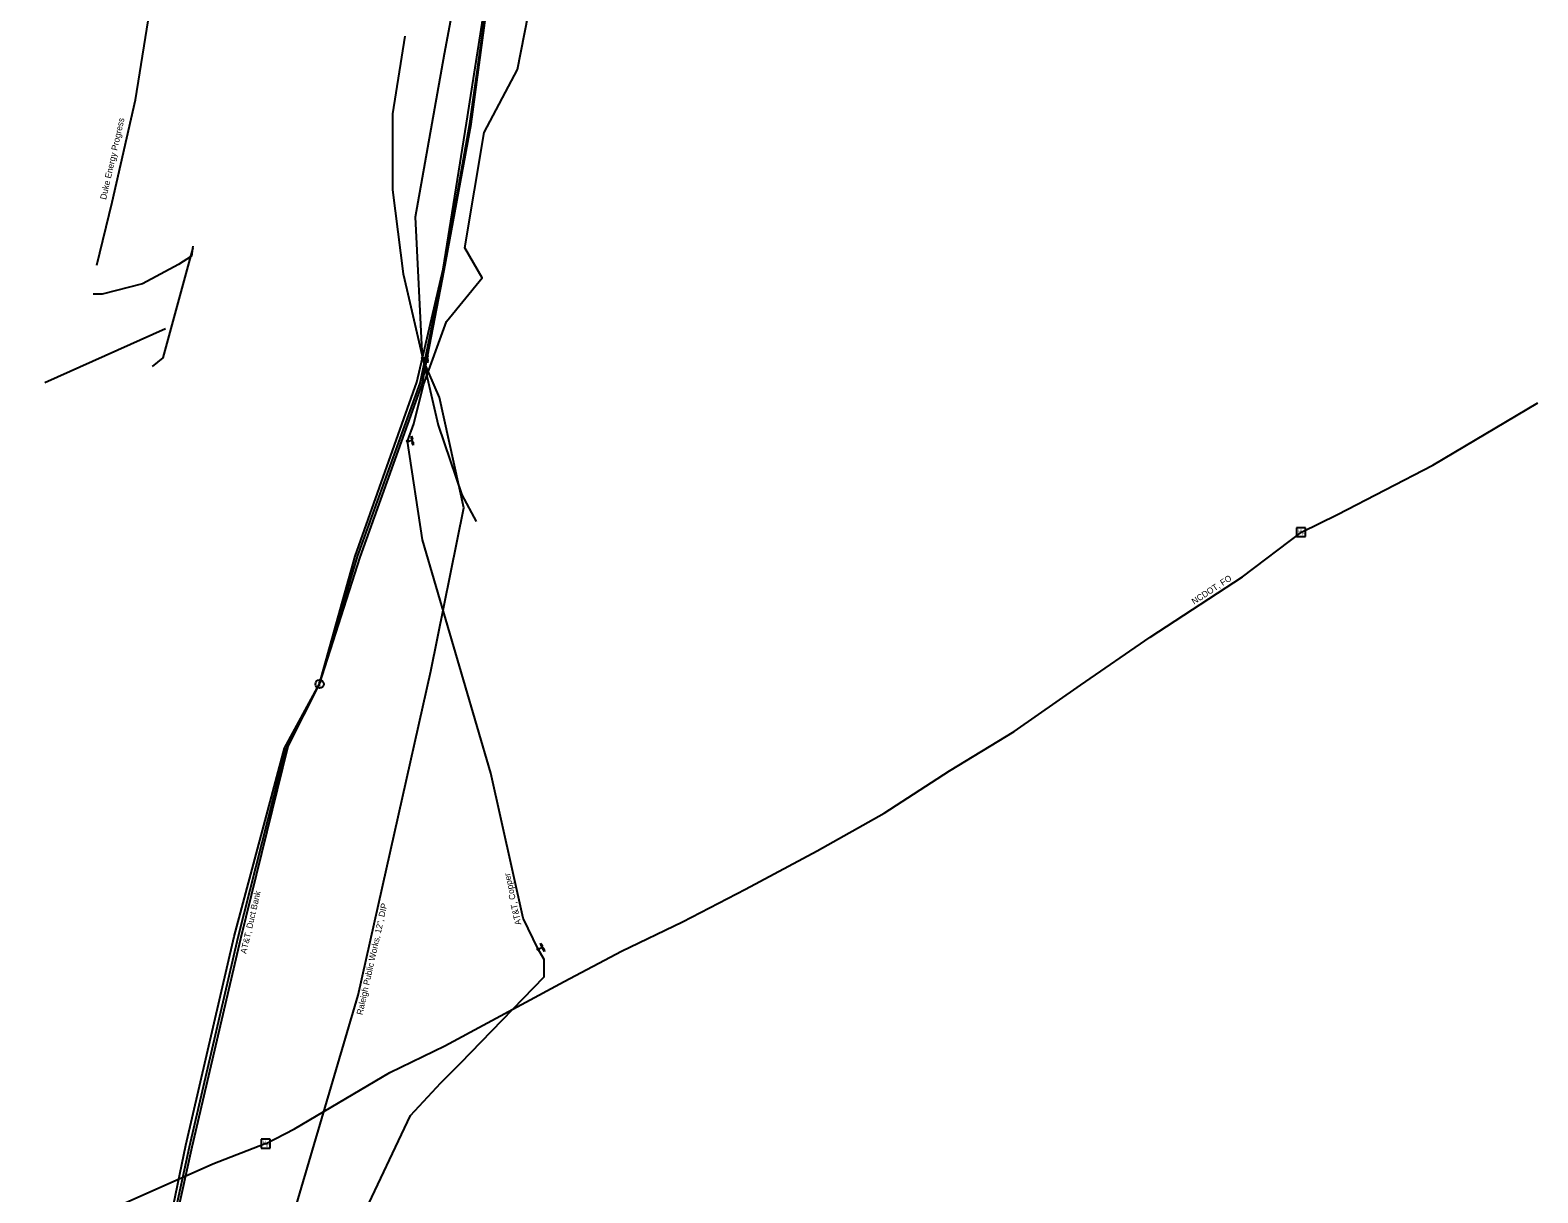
# Model space of a CAD drawing. Extents: x 2070721 to 2083039, y 729290 to 737883.
# Drawn here: x 2082068 to 2083039, y 735399 to 736148 of the extents above; entities that cross this region are included whole.
import ezdxf

# ---------------------------------------------------------------- set-up
doc = ezdxf.new("R2010")
doc.units = 0
for name, color, linetype in [('Exist Utilities Gas UG Line SUE LOS B Cogo Comment', 7, 'Continuous'), ('Exist Utilities Gas Valve CELL', 7, 'Continuous'), ('Exist Utilities Power Pole CELL', 7, 'Continuous'), ('Exist Utilities Power Pole Cogo Elevation', 7, 'Continuous'), ('Exist Utilities Power UG Cable SUE LOS B Cogo Number', 7, 'Continuous'), ('Exist Utilities Telephone UG Cable SUE LOS C Cogo Point CELL', 7, 'Continuous'), ('Exist Utilities Telephone UG FO SUE LOS B Cogo Number', 7, 'Continuous'), ('Exist Utilities TV Hand Hole Cogo Elevation', 7, 'Continuous'), ('Exist Utilities TV Hand Hole Cogo Number', 7, 'Continuous'), ('Exist Utilities TV Pedestal Cogo Elevation', 7, 'Continuous'), ('Exist Utilities TV UG Cable SUE LOS C Cogo Comment', 7, 'Continuous'), ('Exist Utilities TV UG Cable SUE LOS C Cogo Point CELL', 7, 'Continuous'), ('Exist Utilities Water Fire Hydrant Cogo Elevation', 7, 'Continuous'), ('Exist Utilities Water Meter CELL', 7, 'Continuous'), ('Exist Utilities Water UG Line SUE Cogo Point CELL', 7, 'Continuous'), ('Exist Utilities Water UG Line SUE LOS B Cogo Point CELL', 7, 'Continuous')]:
    doc.layers.add(name, color=color, linetype=linetype)

msp = doc.modelspace()

# ---------------------------------------------------------------- linework, layer by layer
at = {"layer": 'Exist Utilities Gas Valve CELL'}
msp.add_line((2082154.94, 735955.71), (2082077.21, 735921.08), dxfattribs=at)
at = {"layer": 'Exist Utilities Power Pole CELL'}
for points in [[(2082121.11, 735111.12), (2082125.96, 735163.62), (2082138.7, 735257.13), (2082145.62, 735320.66), (2082168.01, 735429.9), (2082199.18, 735564.38), (2082231.58, 735685.7), (2082254.18, 735727.05), (2082277.17, 735809.42), (2082316.95, 735921.54), (2082334, 735994.14), (2082349.07, 736088.38), (2082364.7, 736188.68), (2082369.94, 736249.54)], [(2082122.2, 735109.35), (2082127.71, 735163.64), (2082140.55, 735257.07), (2082148.23, 735320.74), (2082172.1, 735428.75), (2082203.63, 735562.9), (2082234.11, 735686.98), (2082254.24, 735726.85), (2082280.4, 735808.61), (2082320.45, 735920.23), (2082334.66, 735993.58), (2082351.98, 736087.59), (2082365.57, 736188.21), (2082370.28, 736249.44)], [(2082311, 735883.41), (2082314.93, 735894.57), (2082321.33, 735919.82), (2082336.09, 735960.51), (2082359.13, 735988.75), (2082348, 736007.91), (2082360.44, 736082.28), (2082381.79, 736122.83), (2082393.52, 736182.23), (2082374.75, 736205.67), (2082370.42, 736249.5)], [(2081917.15, 734795.51), (2082009.52, 734932.29), (2082048.72, 734992.73), (2082076.42, 735035.03), (2082121.27, 735105.83), (2082143.4, 735134.38), (2082165.12, 735153.55), (2082206.17, 735181.11), (2082253.91, 735195.11), (2082261.15, 735199.69), (2082263.21, 735230.16), (2082267.94, 735269.33), (2082270.97, 735300.6), (2082279.44, 735366.27), (2082282.16, 735384.08), (2082312.89, 735448.88), (2082332.37, 735470.01), (2082345.07, 735482.69), (2082399.03, 735538.34), (2082399, 735549.46), (2082395.14, 735556.12)]]:
    msp.add_lwpolyline(points, dxfattribs=at)
at = {"layer": 'Exist Utilities Power Pole Cogo Elevation'}
msp.add_lwpolyline([(2082171.66, 736002.61), (2082163.33, 735997.3), (2082140.18, 735984.73), (2082114.23, 735978.24), (2082108.31, 735978.24)], dxfattribs=at)
at = {"layer": 'Exist Utilities Power UG Cable SUE LOS B Cogo Number'}
for p, q in [((2082320.68, 735936.86), (2082323.76, 735937.02)), ((2082320.68, 735936.86), (2082320.68, 735936.86)), ((2082323.92, 735933.89), (2082323.62, 735939.84)), ((2082323.76, 735937.02), (2082323.92, 735933.89))]:
    msp.add_line(p, q, dxfattribs=at)
for points in [[(2082323.62, 735939.84), (2082324.06, 735937.89), (2082323.7, 735938.29), (2082323.41, 735937.89)], [(2082323.92, 735933.89), (2082323.48, 735935.84), (2082323.84, 735935.43), (2082324.13, 735935.83)]]:
    msp.add_lwpolyline(points, close=True, dxfattribs=at)
msp.add_circle((2082320.68, 735936.86), 0.517, dxfattribs=at)
at = {"layer": 'Exist Utilities Telephone UG Cable SUE LOS C Cogo Point CELL'}
msp.add_circle((2082254.32, 735726.94), 2.72, dxfattribs=at)
at = {"layer": 'Exist Utilities Telephone UG FO SUE LOS B Cogo Number'}
for p, q in [((2082883.94, 735827.62), (2082883.94, 735821.9)), ((2082889.66, 735827.62), (2082883.94, 735827.62)), ((2082886.8, 735824.76), (2082886.8, 735824.76)), ((2082889.66, 735821.9), (2082889.66, 735827.62)), ((2082883.94, 735821.9), (2082889.66, 735821.9)), ((2082216.66, 735433.67), (2082216.66, 735427.95)), ((2082222.38, 735433.67), (2082216.66, 735433.67)), ((2082216.66, 735427.95), (2082222.38, 735427.95)), ((2082219.52, 735430.81), (2082219.52, 735430.81)), ((2082222.38, 735427.95), (2082222.38, 735433.67))]:
    msp.add_line(p, q, dxfattribs=at)
at = {"layer": 'Exist Utilities TV Pedestal Cogo Elevation'}
msp.add_lwpolyline([(2082320.68, 735936.86), (2082316.05, 736027.92), (2082334.72, 736133.01), (2082351.23, 736221.26), (2082359.3, 736290.13)], dxfattribs=at)
at = {"layer": 'Exist Utilities TV UG Cable SUE LOS C Cogo Comment'}
msp.add_line((2082172.58, 736009), (2082171.71, 736002.6), dxfattribs=at)
for points in [[(2082110.71, 735996.86), (2082120.65, 736037.47), (2082135.66, 736103.41), (2082145.82, 736166.3), (2082140.52, 736183.81), (2082144.17, 736185.75)], [(2082309.34, 736144.29), (2082301.38, 736094.4), (2082301.38, 736045.28), (2082308.21, 735991.19), (2082310.45, 735981.19), (2082330.65, 735893.68), (2082346.06, 735848.77), (2082355.29, 735831.7)], [(2082172.61, 736008.03), (2082153.24, 735937.02), (2082146.5, 735931.49)]]:
    msp.add_lwpolyline(points, dxfattribs=at)
at = {"layer": 'Exist Utilities TV UG Cable SUE LOS C Cogo Point CELL'}
for points in [[(2082120.86, 735106.65), (2082121.53, 735109.26), (2082126.82, 735163.37), (2082139.88, 735257.28), (2082147.13, 735321.1), (2082170.45, 735428.84), (2082201.87, 735563.79), (2082232.74, 735685.94), (2082254.12, 735726.65), (2082278.69, 735809.1), (2082319.03, 735920.81), (2082334.41, 735993.71), (2082351.13, 736088.05), (2082365.28, 736188.35), (2082370.12, 736249.49)], [(2082219.49, 735430.7), (2082238.07, 735440.45), (2082299.53, 735476.69), (2082335.09, 735493.88), (2082411.86, 735535.35), (2082448.95, 735554.91), (2082488.14, 735573.69), (2082528.87, 735594.87), (2082574.9, 735619.48), (2082618.09, 735643.71), (2082660.32, 735671.04), (2082701.93, 735696.41), (2082744.65, 735726.21), (2082789.53, 735757.04), (2082848.96, 735795.96), (2082887.04, 735824.81), (2082910.34, 735836.2), (2082971.65, 735868.04), (2083039.4, 735908.05)], [(2082125.22, 735390.95), (2082185.5, 735417.81), (2082219.3, 735430.92)]]:
    msp.add_lwpolyline(points, dxfattribs=at)
at = {"layer": 'Exist Utilities Water Fire Hydrant Cogo Elevation'}
msp.add_lwpolyline([(2082395.14, 735556.12), (2082385.51, 735576.05), (2082364.67, 735669.41), (2082320.62, 735819.86), (2082311, 735883.41)], dxfattribs=at)
at = {"layer": 'Exist Utilities Water UG Line SUE Cogo Point CELL'}
for p, q in [((2082311, 735883.41), (2082314.05, 735883.87)), ((2082311, 735883.41), (2082311, 735883.41)), ((2082314.52, 735880.77), (2082313.63, 735886.67)), ((2082314.05, 735883.87), (2082314.52, 735880.77)), ((2082395.14, 735556.12), (2082397.92, 735557.46)), ((2082395.14, 735556.12), (2082395.14, 735556.12)), ((2082399.28, 735554.64), (2082396.69, 735560.01)), ((2082397.92, 735557.46), (2082399.28, 735554.64))]:
    msp.add_line(p, q, dxfattribs=at)
for points in [[(2082313.63, 735886.67), (2082314.26, 735884.77), (2082313.86, 735885.13), (2082313.61, 735884.71)], [(2082314.52, 735880.77), (2082313.88, 735882.67), (2082314.29, 735882.31), (2082314.53, 735882.73)], [(2082396.69, 735560.01), (2082397.85, 735558.38), (2082397.36, 735558.61), (2082397.25, 735558.13)], [(2082399.28, 735554.64), (2082398.11, 735556.26), (2082398.61, 735556.04), (2082398.72, 735556.51)]]:
    msp.add_lwpolyline(points, close=True, dxfattribs=at)
for centre in [(2082311, 735883.41), (2082395.14, 735556.12)]:
    msp.add_circle(centre, 0.517, dxfattribs=at)
at = {"layer": 'Exist Utilities Water UG Line SUE LOS B Cogo Point CELL'}
msp.add_lwpolyline([(2082136.84, 735123.04), (2082168.96, 735173.67), (2082194.75, 735239.91), (2082279.19, 735526.38), (2082326.09, 735735.17), (2082347.15, 735840.56), (2082331.47, 735911.49), (2082320.68, 735936.86)], dxfattribs=at)

# ---------------------------------------------------------------- texts
at = {"layer": 'Exist Utilities Gas UG Line SUE LOS B Cogo Comment'}
for s, rotation, p in [('NCDOT, FO', 33.22031, (2082817.9, 735778.01)), ('AT&T, Duct Bank', 76.8935, (2082207.05, 735552.84))]:
    msp.add_text(s, height=4, rotation=rotation, dxfattribs=at).set_placement(p)
at = {"layer": 'Exist Utilities Telephone UG Cable SUE LOS C Cogo Point CELL'}
msp.add_text('T', height=3.5, dxfattribs=at).set_placement((2082253.15, 735724.93))
at = {"layer": 'Exist Utilities Telephone UG FO SUE LOS B Cogo Number'}
for p in [(2082884.72, 735824.17), (2082887.29, 735822.7), (2082217.44, 735430.22), (2082220.01, 735428.75)]:
    msp.add_text('H', height=2.5, dxfattribs=at).set_placement(p)
at = {"layer": 'Exist Utilities TV Hand Hole Cogo Elevation'}
msp.add_text('AT&T, Copper', height=4, rotation=102.58143, dxfattribs=at).set_placement((2082384.34, 735572.12))
at = {"layer": 'Exist Utilities TV Hand Hole Cogo Number'}
msp.add_text('Raleigh Public Works, 12", DIP', height=4, rotation=77.3401, dxfattribs=at).set_placement((2082281.93, 735513.47))
at = {"layer": 'Exist Utilities Water Meter CELL'}
msp.add_text('Duke Energy Progress', height=4, rotation=77.17621, dxfattribs=at).set_placement((2082116.65, 736038.77))

doc.saveas('drawing.dxf')
